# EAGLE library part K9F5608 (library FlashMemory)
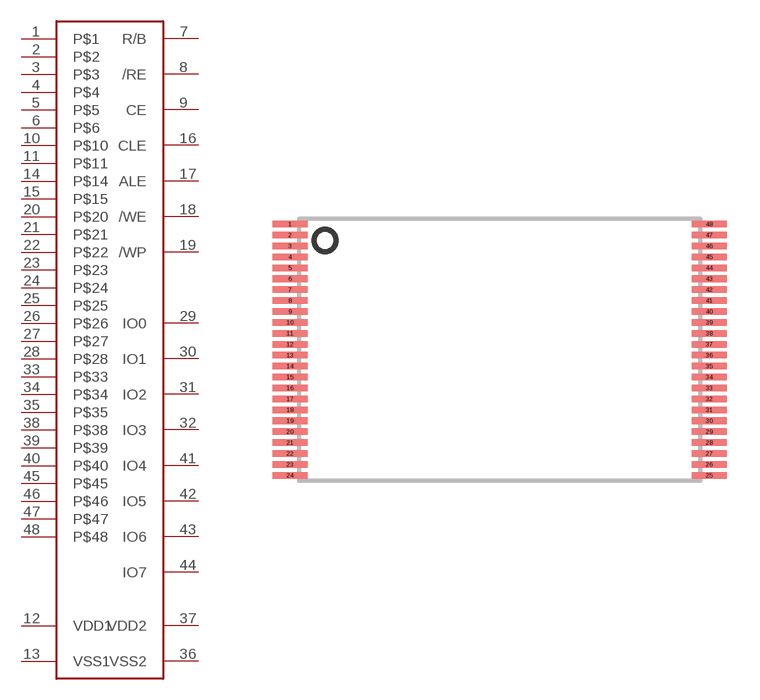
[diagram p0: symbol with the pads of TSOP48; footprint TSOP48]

Designator prefix -

## K9F5608  [TSOP48]
1  P$1  nc
2  P$2  nc
3  P$3  nc
4  P$4  nc
5  P$5  nc
6  P$6  nc
7  R/B  out
8  /RE  in
9  CE  in
10  P$10  nc
11  P$11  nc
12  VDD1  pwr
13  VSS1  pwr
14  P$14  nc
15  P$15  nc
16  CLE  in
17  ALE  in
18  /WE  in
19  /WP  in
20  P$20  nc
21  P$21  nc
22  P$22  nc
23  P$23  nc
24  P$24  nc
25  P$25  nc
26  P$26  nc
27  P$27  nc
28  P$28  nc
29  IO0
30  IO1
31  IO2
32  IO3
33  P$33  nc
34  P$34  nc
35  P$35  nc
36  VSS2  pwr
37  VDD2  pwr
38  P$38  nc
39  P$39  nc
40  P$40  nc
41  IO4
42  IO5
43  IO6
44  IO7
45  P$45  nc
46  P$46  nc
47  P$47  nc
48  P$48  nc

## Footprint TSOP48 (pad centres in mm)
Thin Small Outline Package
smd 1.6 x 0.3: 1 -9.6,5.75; 2 -9.6,5.25; 3 -9.6,4.75; 4 -9.6,4.25; 5 -9.6,3.75; 6 -9.6,3.25; 7 -9.6,2.75; 8 -9.6,2.25; 9 -9.6,1.75; 10 -9.6,1.25; 11 -9.6,0.75; 12 -9.6,0.25; 13 -9.6,-0.25; 14 -9.6,-0.75; 15 -9.6,-1.25; 16 -9.6,-1.75; 17 -9.6,-2.25; 18 -9.6,-2.75; 19 -9.6,-3.25; 20 -9.6,-3.75; 21 -9.6,-4.25; 22 -9.6,-4.75; 23 -9.6,-5.25; 24 -9.6,-5.75; 25 9.6,-5.75; 26 9.6,-5.25; 27 9.6,-4.75; 28 9.6,-4.25; 29 9.6,-3.75; 30 9.6,-3.25; 31 9.6,-2.75; 32 9.6,-2.25; 33 9.6,-1.75; 34 9.6,-1.25; 35 9.6,-0.75; 36 9.6,-0.25; 37 9.6,0.25; 38 9.6,0.75; 39 9.6,1.25; 40 9.6,1.75; 41 9.6,2.25; 42 9.6,2.75; 43 9.6,3.25; 44 9.6,3.75; 45 9.6,4.25; 46 9.6,4.75; 47 9.6,5.25; 48 9.6,5.75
